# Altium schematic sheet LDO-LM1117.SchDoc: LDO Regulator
size A4; Organization: Team Ashwathama; Address1: Colorado Boulder; Address2: Author- Satya Mehta; Address3: Self Checkout Shopping Cart; DocumentNumber: 1; Revision: 1.0; SheetNumber: 4; SheetTotal: 7
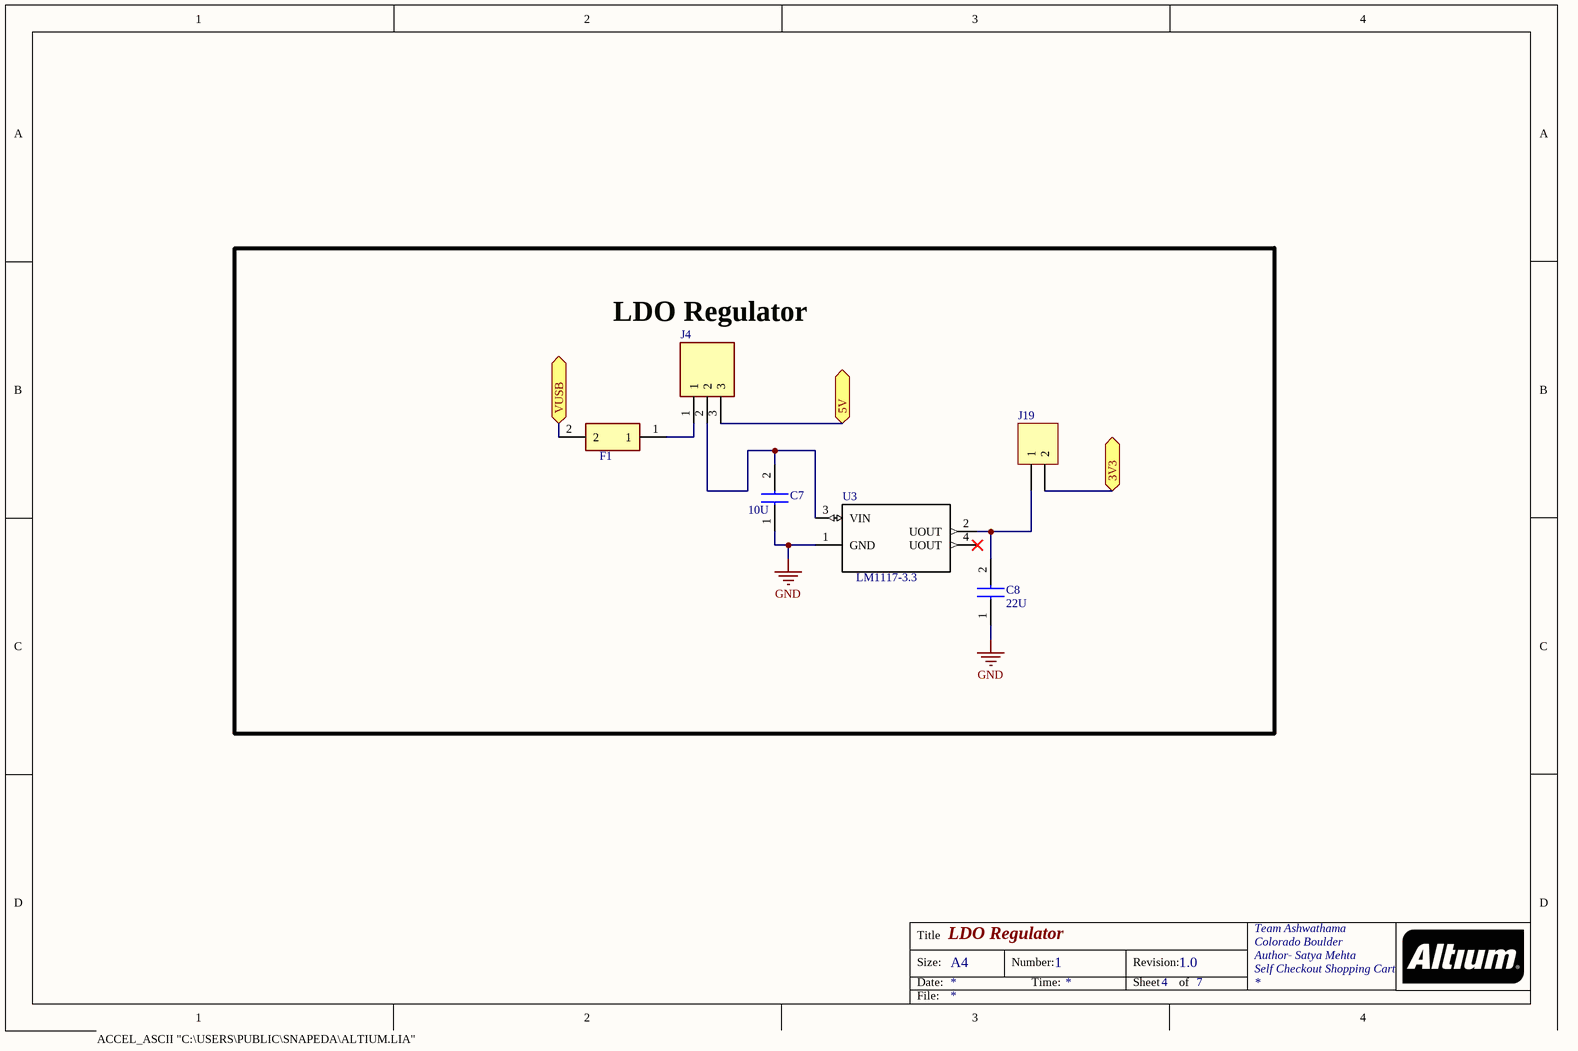
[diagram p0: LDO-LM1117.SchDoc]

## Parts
C7  value 10U  [CAPC6153X300N]  (hidden comment: KCM55LR71E156KH01K)
C8  value 22U  [CAPC3225X270N]  (hidden comment: GRM32ER71C226KEA8L)
F1  MF-MSMF050-2  [FUSC4632X85N]  (value not drawn)
J4  61900311121  [SHDR3W64P0X254_1X3_766X580X1175P]  (value not drawn)
J19  Header 2  [HDR1X2]  (value not drawn)
U3  LM1117-3.3  [*SOT-223]

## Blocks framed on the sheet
LDO Regulator: C7 C8 F1 J4 J19 U3

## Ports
3V3, 5V, VUSB

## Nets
GND: C7.1 C8.1 U3.1(GND)
3V3: J19.2 ; port 3V3
5V: J4.3 ; port 5V
VUSB: F1.2 ; port VUSB
NetC7_2: C7.2 J4.2 U3.3(VIN)
NetC8_2: C8.2 J19.1 U3.2(UOUT)
NetF1_1: F1.1 J4.1

Not connected (* = marked no-connect by the designer): U3 4(UOUT)*

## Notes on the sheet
- ACCEL_ASCII "C:\USERS\PUBLIC\SNAPEDA\ALTIUM.LIA"
  (asciiHeader
  (asciiVersion 5 0)
  (fileAuthor "(c) SnapEDA 2016 (snapeda.com)")
  (copyright "This work is licensed under a Creative Commons Attribution-ShareAlike 4.0 International License (CC BY-SA) with Design Exception 1.0")
  (fileUnits mm)
  )
  (library "Library"
  (padStyleDef "SSX45Y13"
  (holeDiam 0)
  (startRange 1)
  (endRange 2)
  (padShape (layerNumRef 1) (padShapeType Rect) (shapeWidth 0.45) (shapeHeight 1.38))
  (padShape (layerNumRef 2) (padShapeType Rect) (shapeWidth 0) (shapeHeight 0))
  (padShape (layerType Signal) (padShapeType Rect) (shapeWidth 0) (shapeHeight 0))
  (padShape (padShapeType Rect) (shapeWidth 0.45) (shapeHeight 1.38))
  (padShape (padShapeType Rect) (shapeWidth 0.45) (shapeHeight 1.38))
  (padShape (layerType Plane) (padShapeType NoConnect) (shapeWidth 0) (shapeHeight 0))
  (padShape (layerType NonSignal) (padShapeType Oval) (shapeWidth 0) (shapeHeight 0))
  )
  (padStyleDef "SSX14Y21"
  (holeDiam 0)
  (startRange 1)
  (endRange 2)
  (padShape (layerNumRef 1) (padShapeType Rect) (shapeWidth 1.4) (shapeHeight 2.1))
  (padShape (layerNumRef 2) (padShapeType Rect) (shapeWidth 0) (shapeHeight 0))
  (padShape (layerType Signal) (padShapeType Rect) (shapeWidth 0) (shapeHeight 0))
  (padShape (padShapeType Rect) (shapeWidth 1.4) (shapeHeight 2.1))
  (padShape (padShapeType Rect) (shapeWidth 1.4) (shapeHeight 2.1))
  (padShape (layerType Plane) (padShapeType NoConnect) (shapeWidth 0) (shapeHeight 0))
  (padShape (layerType NonSignal) (padShapeType Oval) (shapeWidth 0) (shapeHeight 0))
  )
  (padStyleDef "SSX13Y21"
  (holeDiam 0)
  (startRange 1)
  (endRange 2)
  (padShape (layerNumRef 1) (padShapeType Rect) (shapeWidth 1.375) (shapeHeight 2.1))
  (padShape (layerNumRef 2) (padShapeType Rect) (shapeWidth 0) (shapeHeight 0))
  (padShape (layerType Signal) (padShapeType Rect) (shapeWidth 0) (shapeHeight 0))
  (padShape (padShapeType Rect) (shapeWidth 1.375) (shapeHeight 2.1))
  (padShape (padShapeType Rect) (shapeWidth 1.375) (shapeHeight 2.1))
  (padShape (layerType Plane) (padShapeType NoConnect) (shapeWidth 0) (shapeHeight 0))
  (padShape (layerType NonSignal) (padShapeType Oval) (shapeWidth 0) (shapeHeight 0))
  )
  (padStyleDef "DUD60"
  (holeDiam 0.6)
  (isHolePlated False)
  (startRange 1)
  (endRange 2)
  (padShape (layerNumRef 1) (padShapeType Oval) (shapeWidth 0.6) (shapeHeight 0.6))
  (padShape (layerNumRef 2) (padShapeType Oval) (shapeWidth 0.6) (shapeHeight 0.6))
  (padShape (layerType Signal) (padShapeType Oval) (shapeWidth 0.6) (shapeHeight 0.6))
  (padShape (layerType Plane) (padShapeType NoConnect) (shapeWidth 0) (shapeHeight 0))
  (padShape (layerType NonSignal) (padShapeType Oval) (shapeWidth 0) (shapeHeight 0))
  )
  (padStyleDef "SSX10Y10"
  (holeDiam 0)
  (startRange 1)
  (endRange 2)
  (padShape (layerNumRef 1) (padShapeType Rect) (shapeWidth 0.1) (shapeHeight 0.1))
  (padShape (layerNumRef 2) (padShapeType Rect) (shapeWidth 0) (shapeHeight 0))
  (padShape (layerType Signal) (padShapeType Rect) (shapeWidth 0) (shapeHeight 0))
  (padShape (padShapeType Rect) (shapeWidth 0) (shapeHeight 0))
  (padShape (padShapeType Rect) (shapeWidth 0) (shapeHeight 0))
  (padShape (layerType Plane) (padShapeType NoConnect) (shapeWidth 0) (shapeHeight 0))
  (padShape (layerType NonSignal) (padShapeType Oval) (shapeWidth 0) (shapeHeight 0))
  )
  (textStyleDef "(Default)"
  (font
  (fontType Stroke)
  (fontFamily Modern)
  (fontFace "Quality")
  (fontHeight 3.54)
  )
  (textStyleAllowTType True)
  (textStyleDisplayTType False)
  )
  (textStyleDef "(PinStyle)"
  (font
  (fontType Stroke)
  (fontFamily SanSerif)
  (fontFace "QUALITY")
  (fontHeight 3.54)
  (strokeWidth 0.001)
  )
  (font
  (fontType TrueType)
  (fontFamily Modern)
  (fontFace "Times New Roman")
  (fontHeight 3.54)
  (strokeWidth 0.19843)
  (fontWeight 400)
  (fontCharSet 0)
  (fontOutPrecision 7)
  (fontClipPrecision 32)
  (fontQuality 1)
  (fontPitchAndFamily 6)
  )
  (textStyleAllowTType True)
  (textStyleDisplayTType False)
  )
  (textStyleDef "(LabelStyle)"
  (font
  (fontType Stroke)
  (fontFamily SanSerif)
  (fontFace "QUALITY")
  (fontHeight 3.54)
  (strokeWidth 0.001)
  )
  (font
  (fontType TrueType)
  (fontFamily Modern)
  (fontFace "Times New Roman")
  (fontHeight 3)
  (strokeWidth 0.19843)
  (fontWeight 400)
  (fontCharSet 0)
  (fontOutPrecision 7)
  (fontClipPrecision 32)
  (fontQuality 1)
  (fontPitchAndFamily 6)
  )
  (textStyleAllowTType True)
  (textStyleDisplayTType False)
  )
  (patternDefExtended "*TE_1932788-1"
  (originalName "*TE_1932788-1")
  (patternGraphicsNameRef "Primary")
  (patternGraphicsDef
  (patternGraphicsNameDef "Primary")
  (multiLayer
  (pad (padNum 3) (padStyleRef "SSX45Y13") (pt 0 0))
  (pad (padNum SH1) (padStyleRef "SSX14Y21") (pt -2.5 -0.36))
  (pad (padNum SH2) (padStyleRef "SSX14Y21") (pt 2.5 -0.36))
  (pad (padNum SH5) (padStyleRef "SSX13Y21") (pt -0.9375 -2.71))
  (pad (padNum 2) (padStyleRef "SSX45Y13") (pt -0.65 0))
  (pad (padNum 4) (padStyleRef "SSX45Y13") (pt 0.65 0))
  (pad (padNum 1) (padStyleRef "SSX45Y13") (pt -1.3 0))
  (pad (padNum 5) (padStyleRef "SSX45Y13") (pt 1.3 0))
  (pad (padNum SH4) (padStyleRef "SSX13Y21") (pt 0.9375 -2.71))
  (pad (padNum None) (padStyleRef "DUD60") (pt -3.95 -2.66))
  (pad (padNum None) (padStyleRef "DUD60") (pt 3.95 -2.66))
  (pad (padNum SH3) (padStyleRef "SSX10Y10") (pt 4 -3.5))
  (pad (padNum SH6) (padStyleRef "SSX10Y10") (pt -4 -3.5))
  )
  (layerContents (layerNumRef 1)
  (pcbPoly
  (pt 3.65 -2.66)
  (pt 3.65 -2.31)
  (pt 3.65 -2.30215)
  (pt 3.65082 -2.28646)
  (pt 3.65246 -2.27083)
  (pt 3.65492 -2.25531)
  (pt 3.65819 -2.23994)
  (pt 3.66226 -2.22477)
  (pt 3.66711 -2.20983)
  (pt 3.67274 -2.19516)
  (pt 3.67913 -2.1808)
  (pt 3.68626 -2.1668)
  (pt 3.69412 -2.1532)
  (pt 3.70268 -2.14002)
  (pt 3.71191 -2.12731)
  (pt 3.7218 -2.1151)
  (pt 3.73231 -2.10342)
  (pt 3.74342 -2.09231)
  (pt 3.7551 -2.0818)
  (pt 3.76731 -2.07191)
  (pt 3.78002 -2.06268)
  (pt 3.7932 -2.05412)
  (pt 3.8068 -2.04627)
  (pt 3.8208 -2.03913)
  (pt 3.83515 -2.03274)
  (pt 3.84982 -2.02711)
  (pt 3.86476 -2.02226)
  (pt 3.87994 -2.01819)
  (pt 3.89531 -2.01492)
  (pt 3.91083 -2.01246)
  (pt 3.92645 -2.01082)
  (pt 3.94214 -2.01)
  (pt 3.95 -2.01)
  (pt 3.95785 -2.01)
  (pt 3.97354 -2.01082)
  (pt 3.98917 -2.01246)
  (pt 4.00469 -2.01492)
  (pt 4.02006 -2.01819)
  (pt 4.03523 -2.02226)
  (pt 4.05017 -2.02711)
  (pt 4.06484 -2.03274)
  (pt 4.0792 -2.03913)
  (pt 4.0932 -2.04626)
  (pt 4.1068 -2.05412)
  (pt 4.11998 -2.06268)
  (pt 4.13269 -2.07191)
  (pt 4.1449 -2.0818)
  (pt 4.15658 -2.09231)
  (pt 4.16769 -2.10342)
  (pt 4.1782 -2.1151)
  (pt 4.18809 -2.12731)
  (pt 4.19732 -2.14002)
  (pt 4.20588 -2.1532)
  (pt 4.21373 -2.1668)
  (pt 4.22087 -2.1808)
  (pt 4.22726 -2.19515)
  (pt 4.23289 -2.20982)
  (pt 4.23774 -2.22476)
  (pt 4.24181 -2.23994)
  (pt 4.24508 -2.25531)
  (pt 4.24754 -2.27083)
  (pt 4.24918 -2.28645)
  (pt 4.25 -2.30214)
  (pt 4.25 -2.31)
  (pt 4.25 -3.01)
  (pt 4.25 -3.01785)
  (pt 4.24918 -3.03354)
  (pt 4.24754 -3.04917)
  (pt 4.24508 -3.06469)
  (pt 4.24181 -3.08006)
  (pt 4.23774 -3.09523)
  (pt 4.23289 -3.11017)
  (pt 4.22726 -3.12484)
  (pt 4.22087 -3.1392)
  (pt 4.21374 -3.1532)
  (pt 4.20588 -3.1668)
  (pt 4.19732 -3.17998)
  (pt 4.18809 -3.19269)
  (pt 4.1782 -3.2049)
  (pt 4.16769 -3.21658)
  (pt 4.15658 -3.22769)
  (pt 4.1449 -3.2382)
  (pt 4.13269 -3.24809)
  (pt 4.11998 -3.25732)
  (pt 4.1068 -3.26588)
  (pt 4.0932 -3.27373)
  (pt 4.0792 -3.28087)
  (pt 4.06485 -3.28726)
  (pt 4.05018 -3.29289)
  (pt 4.03524 -3.29774)
  (pt 4.02006 -3.30181)
  (pt 4.00469 -3.30508)
  (pt 3.98917 -3.30754)
  (pt 3.97355 -3.30918)
  (pt 3.95786 -3.31)
  (pt 3.95 -3.31)
  (pt 3.94215 -3.31)
  (pt 3.92646 -3.30918)
  (pt 3.91083 -3.30754)
  (pt 3.89531 -3.30508)
  (pt 3.87994 -3.30181)
  (pt 3.86477 -3.29774)
  (pt 3.84983 -3.29289)
  (pt 3.83516 -3.28726)
  (pt 3.8208 -3.28087)
  (pt 3.8068 -3.27374)
  (pt 3.7932 -3.26588)
  (pt 3.78002 -3.25732)
  (pt 3.76731 -3.24809)
  (pt 3.7551 -3.2382)
  (pt 3.74342 -3.22769)
  (pt 3.73231 -3.21658)
  (pt 3.7218 -3.2049)
  (pt 3.71191 -3.19269)
  (pt 3.70268 -3.17998)
  (pt 3.69412 -3.1668)
  (pt 3.68627 -3.1532)
  (pt 3.67913 -3.1392)
  (pt 3.67274 -3.12485)
  (pt 3.66711 -3.11018)
  (pt 3.66226 -3.09524)
  (pt 3.65819 -3.08006)
  (pt 3.65492 -3.06469)
  (pt 3.65246 -3.04917)
  (pt 3.65082 -3.03355)
  (pt 3.65 -3.01786)
  (pt 3.65 -3.01)
  (pt 3.65 -2.66)
  (pt 3.25 -2.66)
  (pt 3.25 -3.01)
  (pt 3.25 -3.02833)
  (pt 3.25192 -3.06494)
  (pt 3.25575 -3.1014)
  (pt 3.26148 -3.1376)
  (pt 3.26911 -3.17346)
  (pt 3.2786 -3.20887)
  (pt 3.28992 -3.24374)
  (pt 3.30306 -3.27797)
  (pt 3.31797 -3.31146)
  (pt 3.33462 -3.34412)
  (pt 3.35295 -3.37587)
  (pt 3.37291 -3.40662)
  (pt 3.39446 -3.43628)
  (pt 3.41753 -3.46477)
  (pt 3.44206 -3.49201)
  (pt 3.46798 -3.51793)
  (pt 3.49523 -3.54246)
  (pt 3.52372 -3.56554)
  (pt 3.55338 -3.58708)
  (pt 3.58412 -3.60705)
  (pt 3.61587 -3.62538)
  (pt 3.64854 -3.64202)
  (pt 3.68203 -3.65694)
  (pt 3.71625 -3.67007)
  (pt 3.75112 -3.6814)
  (pt 3.78653 -3.69089)
  (pt 3.82239 -3.69851)
  (pt 3.8586 -3.70425)
  (pt 3.89506 -3.70808)
  (pt 3.93167 -3.71)
  (pt 3.95 -3.71)
  (pt 3.96833 -3.71)
  (pt 4.00494 -3.70808)
  (pt 4.0414 -3.70425)
  (pt 4.0776 -3.69852)
  (pt 4.11346 -3.69089)
  (pt 4.14887 -3.6814)
  (pt 4.18374 -3.67008)
  (pt 4.21797 -3.65694)
  (pt 4.25146 -3.64203)
  (pt 4.28412 -3.62538)
  (pt 4.31587 -3.60705)
  (pt 4.34662 -3.58709)
  (pt 4.37628 -3.56554)
  (pt 4.40477 -3.54247)
  (pt 4.43201 -3.51794)
  (pt 4.45793 -3.49202)
  (pt 4.48246 -3.46477)
  (pt 4.50554 -3.43628)
  (pt 4.52708 -3.40662)
  (pt 4.54705 -3.37588)
  (pt 4.56538 -3.34413)
  (pt 4.58202 -3.31146)
  (pt 4.59694 -3.27797)
  (pt 4.61007 -3.24375)
  (pt 4.6214 -3.20888)
  (pt 4.63089 -3.17347)
  (pt 4.63851 -3.13761)
  (pt 4.64425 -3.1014)
  (pt 4.64808 -3.06494)
  (pt 4.65 -3.02833)
  (pt 4.65 -3.01)
  (pt 4.65 -2.31)
  (pt 4.65 -2.29167)
  (pt 4.64808 -2.25506)
  (pt 4.64425 -2.2186)
  (pt 4.63852 -2.1824)
  (pt 4.63089 -2.14654)
  (pt 4.6214 -2.11113)
  (pt 4.61008 -2.07626)
  (pt 4.59694 -2.04203)
  (pt 4.58203 -2.00854)
  (pt 4.56538 -1.97588)
  (pt 4.54705 -1.94413)
  (pt 4.52709 -1.91338)
  (pt 4.50554 -1.88372)
  (pt 4.48247 -1.85523)
  (pt 4.45794 -1.82799)
  (pt 4.43202 -1.80207)
  (pt 4.40477 -1.77754)
  (pt 4.37628 -1.75446)
  (pt 4.34662 -1.73292)
  (pt 4.31588 -1.71295)
  (pt 4.28413 -1.69462)
  (pt 4.25146 -1.67798)
  (pt 4.21797 -1.66306)
  (pt 4.18375 -1.64993)
  (pt 4.14888 -1.6386)
  (pt 4.11347 -1.62911)
  (pt 4.07761 -1.62149)
  (pt 4.0414 -1.61575)
  (pt 4.00494 -1.61192)
  (pt 3.96833 -1.61)
  (pt 3.95 -1.61)
  (pt 3.93167 -1.61)
  (pt 3.89506 -1.61192)
  (pt 3.8586 -1.61575)
  (pt 3.8224 -1.62148)
  (pt 3.78654 -1.62911)
  (pt 3.75113 -1.6386)
  (pt 3.71626 -1.64992)
  (pt 3.68203 -1.66306)
  (pt 3.64854 -1.67797)
  (pt 3.61588 -1.69462)
  (pt 3.58413 -1.71295)
  (pt 3.55338 -1.73291)
  (pt 3.52372 -1.75446)
  (pt 3.49523 -1.77753)
  (pt 3.46799 -1.80206)
  (pt 3.44207 -1.82798)
  (pt 3.41754 -1.85523)
  (pt 3.39446 -1.88372)
  (pt 3.37292 -1.91338)
  (pt 3.35295 -1.94412)
  (pt 3.33462 -1.97587)
  (pt 3.31798 -2.00854)
  (pt 3.30306 -2.04203)
  (pt 3.28993 -2.07625)
  (pt 3.2786 -2.11112)
  (pt 3.26911 -2.14653)
  (pt 3.26149 -2.18239)
  (pt 3.25575 -2.2186)
  (pt 3.25192 -2.25506)
  (pt 3.25 -2.29167)
  (pt 3.25 -2.31)
  (pt 3.25 -2.66)
  (pt 3.65 -2.66)
  )
  (pcbPoly
  (pt -4.25 -2.66)
  (pt -4.25 -2.31)
  (pt -4.25 -2.30215)
  (pt -4.24918 -2.28646)
  (pt -4.24754 -2.27083)
  (pt -4.24508 -2.25531)
  (pt -4.24181 -2.23994)
  (pt -4.23774 -2.22477)
  (pt -4.23289 -2.20983)
  (pt -4.22726 -2.19516)
  (pt -4.22087 -2.1808)
  (pt -4.21374 -2.1668)
  (pt -4.20588 -2.1532)
  (pt -4.19732 -2.14002)
  (pt -4.18809 -2.12731)
  (pt -4.1782 -2.1151)
  (pt -4.16769 -2.10342)
  (pt -4.15658 -2.09231)
  (pt -4.1449 -2.0818)
  (pt -4.13269 -2.07191)
  (pt -4.11998 -2.06268)
  (pt -4.1068 -2.05412)
  (pt -4.0932 -2.04627)
  (pt -4.0792 -2.03913)
  (pt -4.06485 -2.03274)
  (pt -4.05018 -2.02711)
  (pt -4.03524 -2.02226)
  (pt -4.02006 -2.01819)
  (pt -4.00469 -2.01492)
  (pt -3.98917 -2.01246)
  (pt -3.97355 -2.01082)
  (pt -3.95786 -2.01)
  (pt -3.95 -2.01)
  (pt -3.94215 -2.01)
  (pt -3.92646 -2.01082)
  (pt -3.91083 -2.01246)
  (pt -3.89531 -2.01492)
  (pt -3.87994 -2.01819)
  (pt -3.86477 -2.02226)
  (pt -3.84983 -2.02711)
  (pt -3.83516 -2.03274)
  (pt -3.8208 -2.03913)
  (pt -3.8068 -2.04626)
  (pt -3.7932 -2.05412)
  (pt -3.78002 -2.06268)
  (pt -3.76731 -2.07191)
  (pt -3.7551 -2.0818)
  (pt -3.74342 -2.09231)
  (pt -3.73231 -2.10342)
  (pt -3.7218 -2.1151)
  (pt -3.71191 -2.12731)
  (pt -3.70268 -2.14002)
  (pt -3.69412 -2.1532)
  (pt -3.68627 -2.1668)
  (pt -3.67913 -2.1808)
  (pt -3.67274 -2.19515)
  (pt -3.66711 -2.20982)
  (pt -3.66226 -2.22476)
  (pt -3.65819 -2.23994)
  (pt -3.65492 -2.25531)
  (pt -3.65246 -2.27083)
  (pt -3.65082 -2.28645)
  (pt -3.65 -2.30214)
  (pt -3.65 -2.31)
  (pt -3.65 -3.01)
  (pt -3.65 -3.01785)
  (pt -3.65082 -3.03354)
  (pt -3.65246 -3.04917)
  (pt -3.65492 -3.06469)
  (pt -3.65819 -3.08006)
  (pt -3.66226 -3.09523)
  (pt -3.66711 -3.11017)
  (pt -3.67274 -3.12484)
  (pt -3.67913 -3.1392)
  (pt -3.68626 -3.1532)
  (pt -3.69412 -3.1668)
  (pt -3.70268 -3.17998)
  (pt -3.71191 -3.19269)
  (pt -3.7218 -3.2049)
  (pt -3.73231 -3.21658)
  (pt -3.74342 -3.22769)
  (pt -3.7551 -3.2382)
  (pt -3.76731 -3.24809)
  (pt -3.78002 -3.25732)
  (pt -3.7932 -3.26588)
  (pt -3.8068 -3.27373)
  (pt -3.8208 -3.28087)
  (pt -3.83515 -3.28726)
  (pt -3.84982 -3.29289)
  (pt -3.86476 -3.29774)
  (pt -3.87994 -3.30181)
  (pt -3.89531 -3.30508)
  (pt -3.91083 -3.30754)
  (pt -3.92645 -3.30918)
  (pt -3.94214 -3.31)
  (pt -3.95 -3.31)
  (pt -3.95785 -3.31)
  (pt -3.97354 -3.30918)
  (pt -3.98917 -3.30754)
  (pt -4.00469 -3.30508)
  (pt -4.02006 -3.30181)
  (pt -4.03523 -3.29774)
  (pt -4.05017 -3.29289)
  (pt -4.06484 -3.28726)
  (pt -4.0792 -3.28087)
  (pt -4.0932 -3.27374)
  (pt -4.1068 -3.26588)
  (pt -4.11998 -3.25732)
  (pt -4.13269 -3.24809)
  (pt -4.1449 -3.2382)
  (pt -4.15658 -3.22769)
  (pt -4.16769 -3.21658)
  (pt -4.1782 -3.2049)
  (pt -4.18809 -3.19269)
  (pt -4.19732 -3.17998)
  (pt -4.20588 -3.1668)
  (pt -4.21373 -3.1532)
  (pt -4.22087 -3.1392)
  (pt -4.22726 -3.12485)
  (pt -4.23289 -3.11018)
  (pt -4.23774 -3.09524)
  (pt -4.24181 -3.08006)
  (pt -4.24508 -3.06469)
  (pt -4.24754 -3.04917)
  (pt -4.24918 -3.03355)
  (pt -4.25 -3.01786)
  (pt -4.25 -3.01)
  (pt -4.25 -2.66)
  (pt -4.65 -2.66)
  (pt -4.65 -3.01)
  (pt -4.65 -3.02833)
  (pt -4.64808 -3.06494)
  (pt -4.64425 -3.1014)
  (pt -4.63852 -3.1376)
  (pt -4.63089 -3.17346)
  (pt -4.6214 -3.20887)
  (pt -4.61008 -3.24374)
  (pt -4.59694 -3.27797)
  (pt -4.58203 -3.31146)
  (pt -4.56538 -3.34412)
  (pt -4.54705 -3.37587)
  (pt -4.52709 -3.40662)
  (pt -4.50554 -3.43628)
  (pt -4.48247 -3.46477)
  (pt -4.45794 -3.49201)
  (pt -4.43202 -3.51793)
  (pt -4.40477 -3.54246)
  (pt -4.37628 -3.56554)
  (pt -4.34662 -3.58708)
  (pt -4.31588 -3.60705)
  (pt -4.28413 -3.62538)
  (pt -4.25146 -3.64202)
  (pt -4.21797 -3.65694)
  (pt -4.18375 -3.67007)
  (pt -4.14888 -3.6814)
  (pt -4.11347 -3.69089)
  (pt -4.07761 -3.69851)
  (pt -4.0414 -3.70425)
  (pt -4.00494 -3.70808)
  (pt -3.96833 -3.71)
  (pt -3.95 -3.71)
  (pt -3.93167 -3.71)
  (pt -3.89506 -3.70808)
  (pt -3.8586 -3.70425)
  (pt -3.8224 -3.69852)
  (pt -3.78654 -3.69089)
  (pt -3.75113 -3.6814)
  (pt -3.71626 -3.67008)
  (pt -3.68203 -3.65694)
  (pt -3.64854 -3.64203)
  (pt -3.61588 -3.62538)
  (pt -3.58413 -3.60705)
  (pt -3.55338 -3.58709)
  (pt -3.52372 -3.56554)
  (pt -3.49523 -3.54247)
  (pt -3.46799 -3.51794)
  (pt -3.44207 -3.49202)
  (pt -3.41754 -3.46477)
  (pt -3.39446 -3.43628)
  (pt -3.37292 -3.40662)
  (pt -3.35295 -3.37588)
  (pt -3.33462 -3.34413)
  (pt -3.31798 -3.31146)
  (pt -3.30306 -3.27797)
  (pt -3.28993 -3.24375)
  (pt -3.2786 -3.20888)
  (pt -3.26911 -3.17347)
  (pt -3.26149 -3.13761)
  (pt -3.25575 -3.1014)
  (pt -3.25192 -3.06494)
  (pt -3.25 -3.02833)
  (pt -3.25 -3.01)
  (pt -3.25 -2.31)
  (pt -3.25 -2.29167)
  (pt -3.25192 -2.25506)
  (pt -3.25575 -2.2186)
  (pt -3.26148 -2.1824)
  (pt -3.26911 -2.14654)
  (pt -3.2786 -2.11113)
  (pt -3.28992 -2.07626)
  (pt -3.30306 -2.04203)
  (pt -3.31797 -2.00854)
  (pt -3.33462 -1.97588)
  (pt -3.35295 -1.94413)
  (pt -3.37291 -1.91338)
  (pt -3.39446 -1.88372)
  (pt -3.41753 -1.85523)
  (pt -3.44206 -1.82799)
  (pt -3.46798 -1.80207)
  (pt -3.49523 -1.77754)
  (pt -3.52372 -1.75446)
  (pt -3.55338 -1.73292)
  (pt -3.58412 -1.71295)
  (pt -3.61587 -1.69462)
  (pt -3.64854 -1.67798)
  (pt -3.68203 -1.66306)
  (pt -3.71625 -1.64993)
  (pt -3.75112 -1.6386)
  (pt -3.78653 -1.62911)
  (pt -3.82239 -1.62149)
  (pt -3.8586 -1.61575)
  (pt -3.89506 -1.61192)
  (pt -3.93167 -1.61)
  (pt -3.95 -1.61)
  (pt -3.96833 -1.61)
  (pt -4.00494 -1.61192)
  (pt -4.0414 -1.61575)
  (pt -4.0776 -1.62148)
  (pt -4.11346 -1.62911)
  (pt -4.14887 -1.6386)
  (pt -4.18374 -1.64992)
  (pt -4.21797 -1.66306)
  (pt -4.25146 -1.67797)
  (pt -4.28412 -1.69462)
  (pt -4.31587 -1.71295)
  (pt -4.34662 -1.73291)
  (pt -4.37628 -1.75446)
  (pt -4.40477 -1.77753)
  (pt -4.43201 -1.80206)
  (pt -4.45793 -1.82798)
  (pt -4.48246 -1.85523)
  (pt -4.50554 -1.88372)
  (pt -4.52708 -1.91338)
  (pt -4.54705 -1.94412)
  (pt -4.56538 -1.97587)
  (pt -4.58202 -2.00854)
  (pt -4.59694 -2.04203)
  (pt -4.61007 -2.07625)
  (pt -4.6214 -2.11112)
  (pt -4.63089 -2.14653)
  (pt -4.63851 -2.18239)
  (pt -4.64425 -2.2186)
  (pt -4.64808 -2.25506)
  (pt -4.65 -2.29167)
  (pt -4.65 -2.31)
  (pt -4.65 -2.66)
  (pt -4.25 -2.66)
  )
  )
  (layerContents (layerNumRef 20)
  (line (pt -3.76 0.34) (pt 3.76 0.34) (width 0.127))
  (line (pt 3.76 0.34) (pt 3.76 -4.11) (width 0.127))
  (line (pt 3.76 -4.11) (pt 3.76 -4.81) (width 0.127))
  (line (pt 3.76 -4.81) (pt -3.76 -4.81) (width 0.127))
  (line (pt -3.76 -4.81) (pt -3.76 -4.11) (width 0.127))
  (line (pt -3.76 -4.11) (pt -3.76 0.34) (width 0.127))
  (attr "RefDes" "" (pt -5.00279 1.59089) (justify LowerLeft) (isVisible True) (textStyleRef "(PinStyle)"))
  (attr "Type" "" (pt -5.30911 -6.81169) (justify LowerLeft) (isVisible True) (textStyleRef "(PinStyle)"))
  (text (pt 0.490973 -4.32808) "PCB EDGE" (justify LowerLeft) (isVisible True) (textStyleRef "(LabelStyle)"))
  (line (pt -3.76 -4.11) (pt 3.76 -4.11) (width 0.127))
  (arc (pt -1.3 0) (radius 0.1) (startAngle 0) (sweepAngle 360) (width 0.2))
  )
  (layerContents (layerNumRef 20)
  (line (pt -3.76 0.34) (pt 3.76 0.34) (width 0.127))
  (line (pt 3.76 0.34) (pt 3.76 -4.11) (width 0.127))
  (line (pt 3.76 -4.11) (pt 3.76 -4.81) (width 0.127))
  (line (pt 3.76 -4.81) (pt -3.76 -4.81) (width 0.127))
  (line (pt -3.76 -4.81) (pt -3.76 -4.11) (width 0.127))
  (line (pt -3.76 -4.11) (pt -3.76 0.34) (width 0.127))
  (attr "RefDes" "" (pt -5.00279 1.59089) (justify LowerLeft) (isVisible True) (textStyleRef "(PinStyle)"))
  (attr "Type" "" (pt -5.30911 -6.81169) (justify LowerLeft) (isVisible True) (textStyleRef "(PinStyle)"))
  (text (pt 0.490973 -4.32808) "PCB EDGE" (justify LowerLeft) (isVisible True) (textStyleRef "(LabelStyle)"))
  (line (pt -3.76 -4.11) (pt 3.76 -4.11) (width 0.127))
  (arc (pt -1.3 0) (radius 0.1) (startAngle 0) (sweepAngle 360) (width 0.2))
  )
  (layerContents (layerNumRef 10)
  (line (pt -4.7 -4.11) (pt -3.3 -4.11) (width 0.0001))
  (line (pt -3.3 -4.11) (pt -2.825 -3.61) (width 0.0001))
  (line (pt -2.825 -3.61) (pt -2.825 -2.51) (width 0.0001))
  (arc (pt -2.3875 -2.4975) (radius 0.437679) (startAngle 92) (sweepAngle 90) (width 0.0001))
  (arc (pt -2.3875 -2.5225) (radius 0.462669) (startAngle 2) (sweepAngle 90) (width 0.0001))
  (line (pt -1.925 -2.51) (pt -1.925 -3.61) (width 0.0001))
  (line (pt -1.925 -3.61) (pt -1.5 -4.11) (width 0.0001))
  (line (pt -1.5 -4.11) (pt 1.5 -4.11) (width 0.0001))
  (line (pt 1.5 -4.11) (pt 1.925 -3.61) (width 0.0001))
  (line (pt 1.925 -3.61) (pt 1.925 -2.51) (width 0.0001))
  (arc (pt 2.3875 -2.5225) (radius 0.462669) (startAngle 88) (sweepAngle 90) (width 0.0001))
  (arc (pt 2.3875 -2.4975) (radius 0.437679) (startAngle 358) (sweepAngle -270) (width 0.0001))
  (line (pt 2.825 -2.51) (pt 2.825 -3.61) (width 0.0001))
  (line (pt 2.825 -3.61) (pt 3.3 -4.11) (width 0.0001))
  (line (pt 3.3 -4.11) (pt 4.9 -4.11) (width 0.0001))
  (arc (pt 3.95 -2.31) (radius 0.3) (startAngle 0) (sweepAngle 90) (width 0.0001))
  (arc (pt 3.95 -2.31) (radius 0.3) (startAngle 90) (sweepAngle 90) (width 0.0001))
  (line (pt 3.65 -2.31) (pt 3.65 -3.01) (width 0.0001))
  (arc (pt 3.95 -3.01) (radius 0.3) (startAngle 180) (sweepAngle 90) (width 0.0001))
  (arc (pt 3.95 -3.01) (radius 0.3) (startAngle 270) (sweepAngle -270) (width 0.0001))
  (line (pt 4.25 -3.01) (pt 4.25 -2.31) (width 0.0001))
  (arc (pt -3.95 -2.31) (radius 0.3) (startAngle 0) (sweepAngle 90) (width 0.0001))
  (arc (pt -3.95 -2.31) (radius 0.3) (startAngle 90) (sweepAngle 90) (width 0.0001))
  (line (pt -4.25 -2.31) (pt -4.25 -3.01) (width 0.0001))
  (arc (pt -3.95 -3.01) (radius 0.3) (startAngle 180) (sweepAngle 90) (width 0.0001))
  (arc (pt -3.95 -3.01) (radius 0.3) (startAngle 270) (sweepAngle -270) (width 0.0001))
  (line (pt -3.65 -3.01) (pt -3.65 -2.31) (width 0.0001))
  )
  (layerContents (layerNumRef 6)
  (line (pt -3.76 -3.96) (pt -3.76 -4.81) (width 0.127))
  (line (pt -3.76 -4.81) (pt 3.76 -4.81) (width 0.127))
  (line (pt 3.76 -4.81) (pt 3.76 -3.96) (width 0.127))
  (line (pt -3.76 -1.36) (pt -3.76 0.34) (width 0.127))
  (line (pt -3.76 0.34) (pt -3.4 0.34) (width 0.127))
  (line (pt 3.4 0.34) (pt 3.76 0.34) (width 0.127))
  (line (pt 3.76 0.34) (pt 3.76 -1.36) (width 0.127))
  (arc (pt -1.3 1.25) (radius 0.1) (startAngle 0) (sweepAngle 360) (width 0.2))
  )
  (layerContents (layerNumRef 5)
  (pcbPoly
  (pt 3.65 -2.66)
  (pt 3.65 -2.31)
  (pt 3.65 -2.30215)
  (pt 3.65082 -2.28646)
  (pt 3.65246 -2.27083)
  (pt 3.65492 -2.25531)
  (pt 3.65819 -2.23994)
  (pt 3.66226 -2.22477)
  (pt 3.66711 -2.20983)
  (pt 3.67274 -2.19516)
  (pt 3.67913 -2.1808)
  (pt 3.68626 -2.1668)
  (pt 3.69412 -2.1532)
  (pt 3.70268 -2.14002)
  (pt 3.71191 -2.12731)
  (pt 3.7218 -2.1151)
  (pt 3.73231 -2.10342)
  (pt 3.74342 -2.09231)
  (pt 3.7551 -2.0818)
  (pt 3.76731 -2.07191)
  (pt 3.78002 -2.06268)
  (pt 3.7932 -2.05412)
  (pt 3.8068 -2.04627)
  (pt 3.8208 -2.03913)
  (pt 3.83515 -2.03274)
  (pt 3.84982 -2.02711)
  (pt 3.86476 -2.02226)
  (pt 3.87994 -2.01819)
  (pt 3.89531 -2.01492)
  (pt 3.91083 -2.01246)
  (pt 3.92645 -2.01082)
  (pt 3.94214 -2.01)
  (pt 3.95 -2.01)
  (pt 3.95785 -2.01)
  (pt 3.97354 -2.01082)
  (pt 3.98917 -2.01246)
  (pt 4.00469 -2.01492)
  (pt 4.02006 -2.01819)
  (pt 4.03523 -2.02226)
  (pt 4.05017 -2.02711)
  (pt 4.06484 -2.03274)
  (pt 4.0792 -2.03913)
  (pt 4.0932 -2.04626)
  (pt 4.1068 -2.05412)
  (pt 4.11998 -2.06268)
  (pt 4.13269 -2.07191)
  (pt 4.1449 -2.0818)
  (pt 4.15658 -2.09231)
  (pt 4.16769 -2.10342)
  (pt 4.1782 -2.1151)
  (pt 4.18809 -2.12731)
  (pt 4.19732 -2.14002)
  (pt 4.20588 -2.1532)
  (pt 4.21373 -2.1668)
  (pt 4.22087 -2.1808)
  (pt 4.22726 -2.19515)
  (pt 4.23289 -2.20982)
  (pt 4.23774 -2.22476)
  (pt 4.24181 -2.23994)
  (pt 4.24508 -2.25531)
  (pt 4.24754 -2.27083)
  (pt 4.24918 -2.28645)
  (pt 4.25 -2.30214)
  (pt 4.25 -2.31)
  (pt 4.25 -3.01)
  (pt 4.25 -3.01785)
  (pt 4.24918 -3.03354)
  (pt 4.24754 -3.04917)
  (pt 4.24508 -3.06469)
  (pt 4.24181 -3.08006)
  (pt 4.23774 -3.09523)
  (pt 4.23289 -3.11017)
  (pt 4.22726 -3.12484)
  (pt 4.22087 -3.1392)
  (pt 4.21374 -3.1532)
  (pt 4.20588 -3.1668)
  (pt 4.19732 -3.17998)
  (pt 4.18809 -3.19269)
  (pt 4.1782 -3.2049)
  (pt 4.16769 -3.21658)
  (pt 4.15658 -3.22769)
  (pt 4.1449 -3.2382)
  (pt 4.13269 -3.24809)
  (pt 4.11998 -3.25732)
  (pt 4.1068 -3.26588)
  (pt 4.0932 -3.27373)
  (pt 4.0792 -3.28087)
  (pt 4.06485 -3.28726)
  (pt 4.05018 -3.29289)
  (pt 4.03524 -3.29774)
  (pt 4.02006 -3.30181)
  (pt 4.00469 -3.30508)
  (pt 3.98917 -3.30754)
  (pt 3.97355 -3.30918)
  (pt 3.95786 -3.31)
  (pt 3.95 -3.31)
  (pt 3.94215 -3.31)
  (pt 3.92646 -3.30918)
  (pt 3.91083 -3.30754)
  (pt 3.89531 -3.30508)
  (pt 3.87994 -3.30181)
  (pt 3.86477 -3.29774)
  (pt 3.84983 -3.29289)
  (pt 3.83516 -3.28726)
  (pt 3.8208 -3.28087)
  (pt 3.8068 -3.27374)
  (pt 3.7932 -3.26588)
  (pt 3.78002 -3.25732)
  (pt 3.76731 -3.24809)
  (pt 3.7551 -3.2382)
  (pt 3.74342 -3.22769)
  (pt 3.73231 -3.21658)
  (pt 3.7218 -3.2049)
  (pt 3.71191 -3.19269)
  (pt 3.70268 -3.17998)
  (pt 3.69412 -3.1668)
  (pt 3.68627 -3.1532)
  (pt 3.67913 -3.1392)
  (pt 3.67274 -3.12485)
  (pt 3.66711 -3.11018)
  (pt 3.66226 -3.09524)
  (pt 3.65819 -3.08006)
  (pt 3.65492 -3.06469)
  (pt 3.65246 -3.04917)
  (pt 3.65082 -3.03355)
  (pt 3.65 -3.01786)
  (pt 3.65 -3.01)
  (pt 3.65 -2.66)
  (pt 3.25 -2.66)
  (pt 3.25 -3.01)
  (pt 3.25 -3.02833)
  (pt 3.25192 -3.06494)
  (pt 3.25575 -3.1014)
  (pt 3.26148 -3.1376)
  (pt 3.26911 -3.17346)
  (pt 3.2786 -3.20887)
  (pt 3.28992 -3.24374)
  (pt 3.30306 -3.27797)
  (pt 3.31797 -3.31146)
  (pt 3.33462 -3.34412)
  (pt

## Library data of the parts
C7 = KCM55LR71E156KH01K: Capacitor; Manufacturer_Name: Murata Electronics
C8 = GRM32ER71C226KEA8L: Capacitor; Manufacturer_Name: Murata Electronics
F1 = MF-MSMF050-2: Fuse; Manufacturer_Name: Bourns; Allied_Number: 70153466
J4 = 61900311121: Connector; Manufacturer_Name: Wurth Elektronik
J19 = Header 2: Header, 2-Pin; Manufacturer_Part_Number: BG301-04-A-0540-L-B; Manufacturer_Name: Global Connector Technology
U3 = LM1117-3.3: 3V3 Low Dropout Regulator; Manufacturer_Part_Number: LM1117MPX-3.3/NOPB; Manufacturer_Name: Texas Instruments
